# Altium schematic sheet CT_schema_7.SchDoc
size 254 x 194 mm
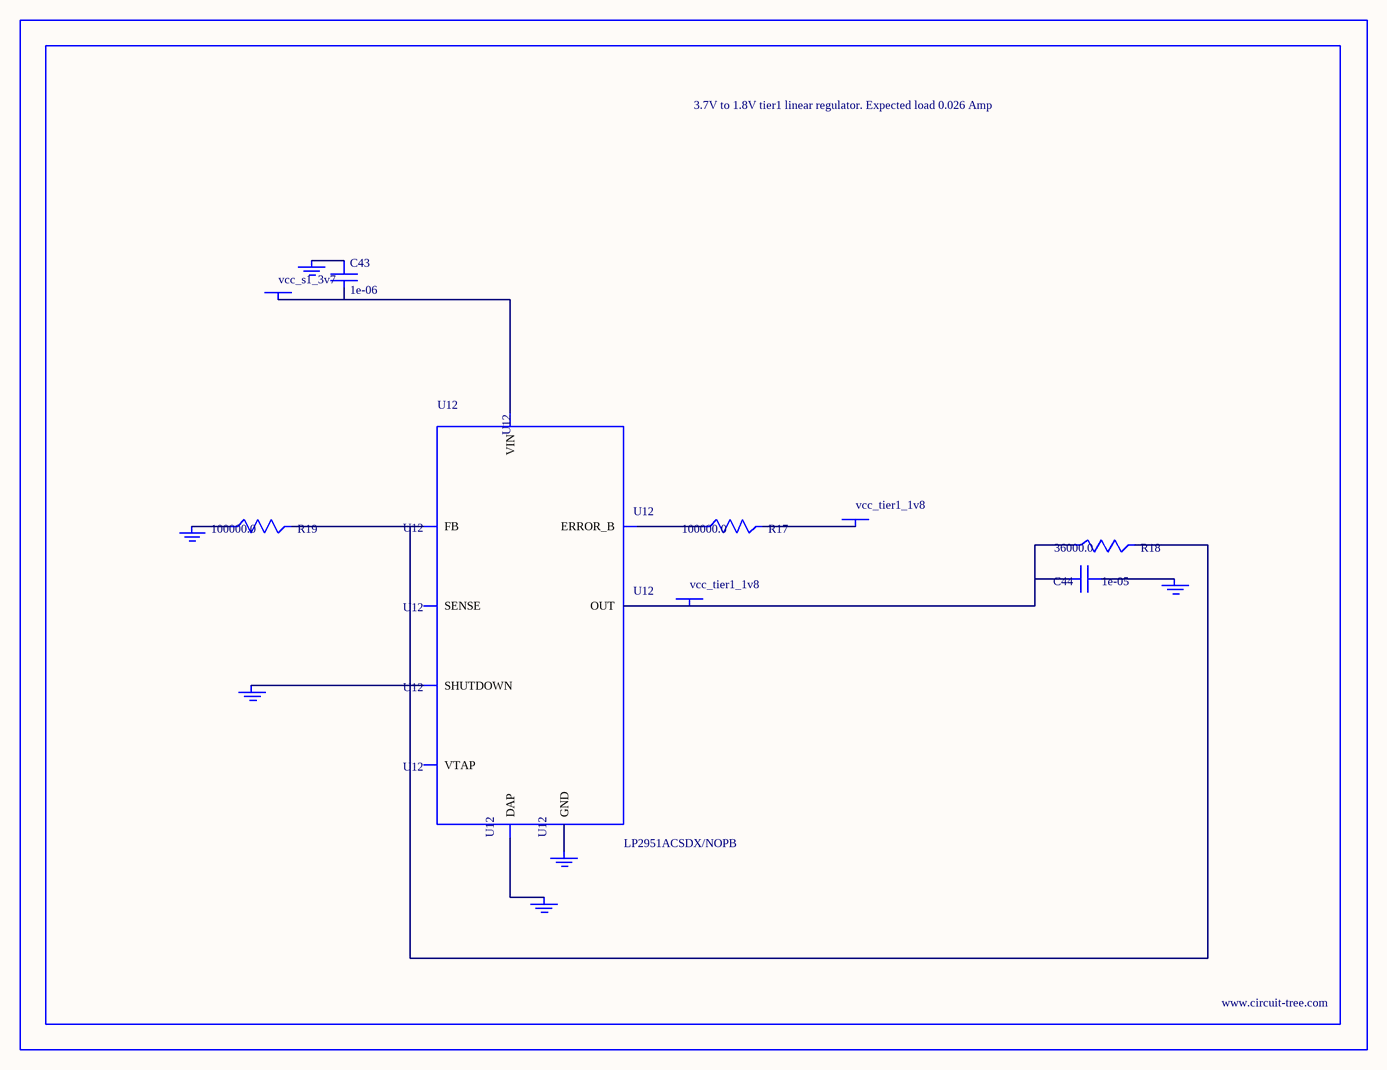
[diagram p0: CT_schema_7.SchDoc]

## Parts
BORDER6  (no value)
C43  1e-06  [C0603]
C44  1e-05  [C0805]
GND_INSTANCE_6_0  (no value)
GND_INSTANCE_6_1  (no value)
GND_INSTANCE_6_2  (no value)
GND_INSTANCE_6_3  (no value)
GND_INSTANCE_6_4  (no value)
GND_INSTANCE_6_5  (no value)
POWER_INSTANCE_6_0  vcc_tier1_1v8
POWER_INSTANCE_6_1  vcc_s1_3v7
POWER_INSTANCE_6_2  vcc_tier1_1v8
R17  100000.0  [R0603]
R18  36000.0  [R0603]
R19  100000.0  [R0603]
U12  LP2951ACSDX/NOPB  [WSON-8]

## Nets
NetC43_1: C43.1 GND_INSTANCE_6_3.0(GND)
NetC43_2: C43.2 POWER_INSTANCE_6_1.0(PWR) U12.8(VIN)
NetC44_1: C44.1 GND_INSTANCE_6_0.0(GND)
NetC44_2: C44.2 POWER_INSTANCE_6_2.0(PWR) R18.1 U12.1(OUT)
NetGND_INSTANCE_6_1_0: GND_INSTANCE_6_1.0(GND) U12.3(SHUTDOWN)
NetGND_INSTANCE_6_2_0: GND_INSTANCE_6_2.0(GND) R19.1
NetGND_INSTANCE_6_4_0: GND_INSTANCE_6_4.0(GND) U12.PAD(DAP)
NetGND_INSTANCE_6_5_0: GND_INSTANCE_6_5.0(GND) U12.4(GND)
NetPOWER_INSTANCE_6_0_0: POWER_INSTANCE_6_0.0(PWR) R17.2
NetR17_1: R17.1 U12.5(ERROR_B)
NetR18_2: R18.2 R19.2 U12.7(FB)

Not connected (* = marked no-connect by the designer): U12 2(SENSE) 6(VTAP)

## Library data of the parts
BORDER6 = BORDER_PAGE6
C43 = C0603C105K3RACTU
C44 = GRM219R60J106ME19D
GND_INSTANCE_6_0-GND_INSTANCE_6_5 = GND
POWER_INSTANCE_6_0-POWER_INSTANCE_6_2 = PWR
R17 R19 = RC0603JR-07100KL
R18 = RC0603JR-0736KL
